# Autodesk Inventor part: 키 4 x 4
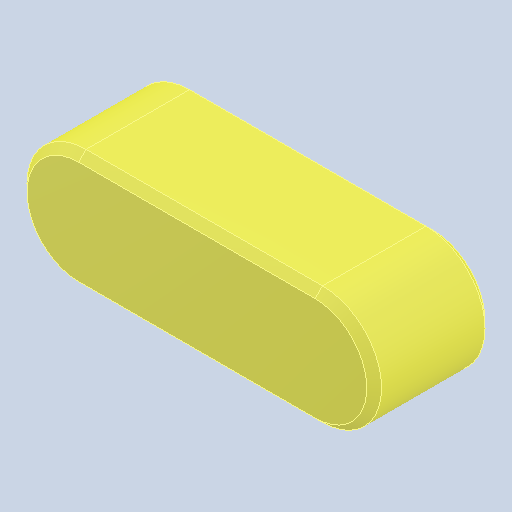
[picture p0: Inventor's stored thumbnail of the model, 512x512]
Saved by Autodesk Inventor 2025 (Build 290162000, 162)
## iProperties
Created: 2025-08
Part Number: 키 4 x 4
Material: 강철, 연강
Description: 키 및 해당 키홈
Document SubType Name: Modeling
Designer: infra02
Density: 7.86 g/cm^3
Appearance: 기본값
Author: jhkim
Sending System: Autodesk Inventor 2026
Preprocessor: ST-DEVELOPER v20.1
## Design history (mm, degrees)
feature "Solid1"
node "솔리드1"
